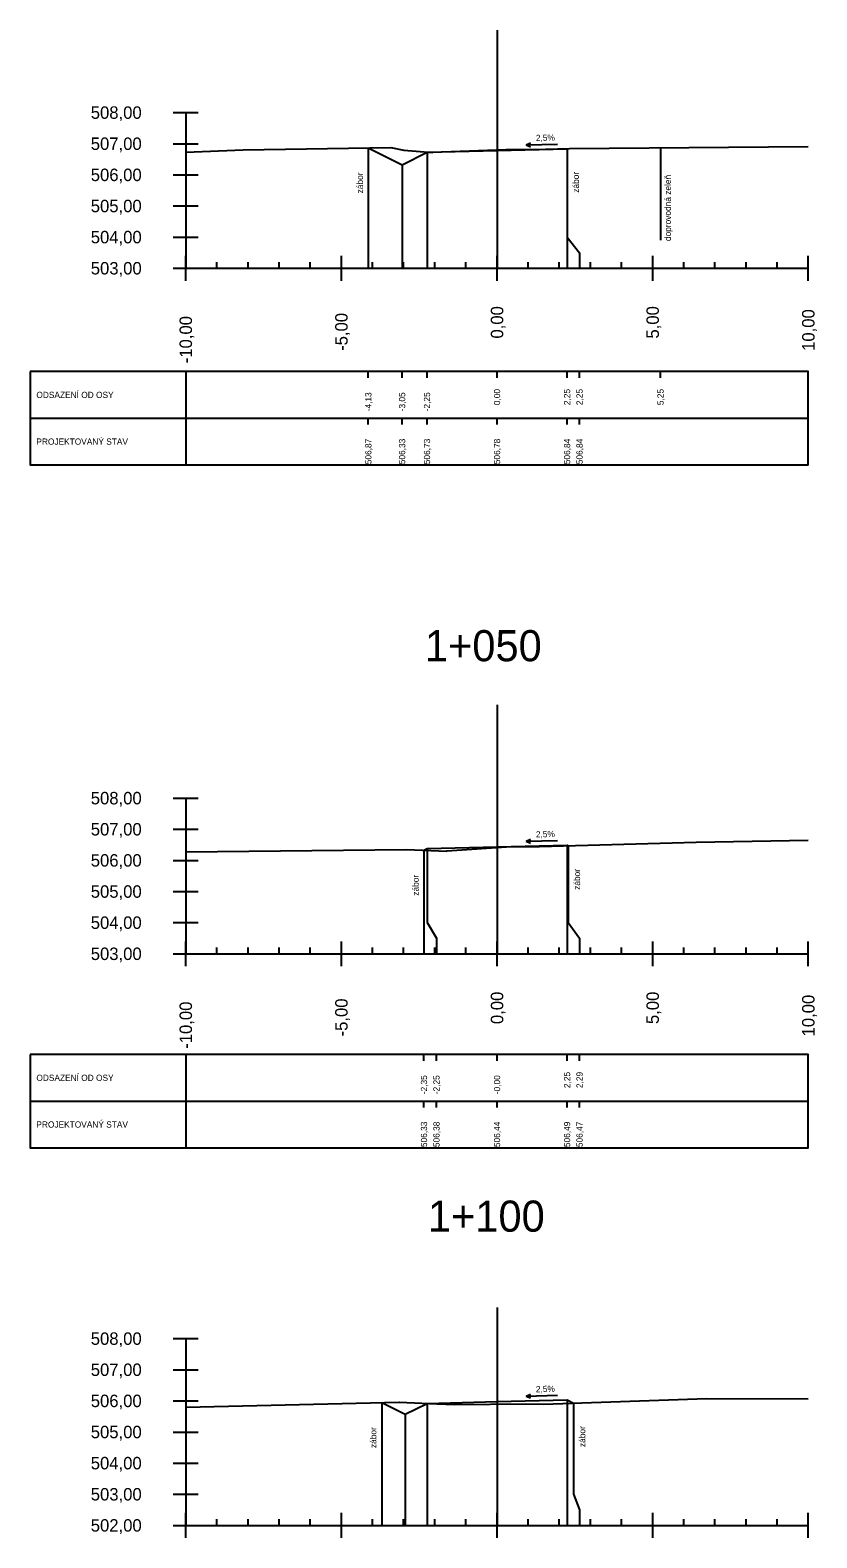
# Model space of a CAD drawing. Extents: x -631407 to -631215, y -1089700 to -1088598.
# Drawn here: x -631344.23 to -631318.96, y -1088856.74 to -1088808.31 of the extents above; entities that cross this region are included whole.
import ezdxf

# ---------------------------------------------------------------- set-up
doc = ezdxf.new("R2010")
doc.units = 0
for name, color, linetype in [('59', 7, 'Continuous'), ('NIVELETA_VYSKY', 7, 'Continuous'), ('REZ_BODY', 7, 'Continuous'), ('REZ_ODSTUPY', 7, 'Continuous'), ('REZ_POPIS', 7, 'Continuous'), ('REZ_RAMY', 7, 'Continuous'), ('REZ_STANICENI', 7, 'Continuous'), ('REZ_SVISLE', 7, 'Continuous'), ('REZ_TENKA', 7, 'Continuous'), ('REZ_TLUSTA', 7, 'Continuous'), ('TABULKA_POPIS', 7, 'Continuous'), ('TEREN', 7, 'Continuous'), ('zábor', 7, 'Continuous')]:
    doc.layers.add(name, color=color, linetype=linetype)

msp = doc.modelspace()

# ---------------------------------------------------------------- linework, layer by layer
at = {"layer": '59'}
for p, q in [((-631339.63, -1088810.959), (-631338.83, -1088810.959)), ((-631339.23, -1088810.959), (-631339.23, -1088815.959)), ((-631339.63, -1088811.959), (-631338.83, -1088811.959)), ((-631339.63, -1088812.959), (-631338.83, -1088812.959)), ((-631339.63, -1088813.959), (-631338.83, -1088813.959)), ((-631339.63, -1088814.959), (-631338.83, -1088814.959)), ((-631339.63, -1088815.959), (-631338.83, -1088815.959)), ((-631339.63, -1088832.981), (-631338.83, -1088832.981)), ((-631339.23, -1088832.981), (-631339.23, -1088837.981)), ((-631339.63, -1088833.981), (-631338.83, -1088833.981)), ((-631339.63, -1088834.981), (-631338.83, -1088834.981)), ((-631339.63, -1088835.981), (-631338.83, -1088835.981)), ((-631339.63, -1088836.981), (-631338.83, -1088836.981)), ((-631339.63, -1088837.981), (-631338.83, -1088837.981)), ((-631339.63, -1088850.343), (-631338.83, -1088850.343)), ((-631339.23, -1088850.343), (-631339.23, -1088856.343)), ((-631339.63, -1088851.343), (-631338.83, -1088851.343)), ((-631339.63, -1088852.343), (-631338.83, -1088852.343)), ((-631339.63, -1088853.343), (-631338.83, -1088853.343)), ((-631339.63, -1088854.343), (-631338.83, -1088854.343)), ((-631339.63, -1088855.343), (-631338.83, -1088855.343)), ((-631339.63, -1088856.343), (-631338.83, -1088856.343))]:
    msp.add_line(p, q, dxfattribs=at)
at = {"layer": 'REZ_RAMY'}
for p, q in [((-631339.23, -1088819.278), (-631339.23, -1088822.278)), ((-631333.365, -1088819.478), (-631333.365, -1088819.278)), ((-631332.28, -1088819.478), (-631332.28, -1088819.278)), ((-631331.48, -1088819.478), (-631331.48, -1088819.278)), ((-631329.23, -1088819.478), (-631329.23, -1088819.278)), ((-631326.98, -1088819.478), (-631326.98, -1088819.278)), ((-631326.58, -1088819.478), (-631326.58, -1088819.278)), ((-631323.979, -1088819.478), (-631323.979, -1088819.278)), ((-631344.23, -1088820.778), (-631319.23, -1088820.778)), ((-631333.365, -1088820.978), (-631333.365, -1088820.778)), ((-631332.28, -1088820.978), (-631332.28, -1088820.778)), ((-631331.48, -1088820.978), (-631331.48, -1088820.778)), ((-631329.23, -1088820.978), (-631329.23, -1088820.778)), ((-631326.98, -1088820.978), (-631326.98, -1088820.778)), ((-631326.58, -1088820.978), (-631326.58, -1088820.778)), ((-631344.23, -1088841.215), (-631344.23, -1088844.215)), ((-631339.23, -1088841.215), (-631339.23, -1088844.215)), ((-631331.577, -1088841.415), (-631331.577, -1088841.215)), ((-631331.177, -1088841.415), (-631331.177, -1088841.215)), ((-631329.23, -1088841.415), (-631329.23, -1088841.215)), ((-631326.98, -1088841.415), (-631326.98, -1088841.215)), ((-631326.58, -1088841.415), (-631326.58, -1088841.215)), ((-631344.23, -1088842.715), (-631319.23, -1088842.715)), ((-631331.577, -1088842.915), (-631331.577, -1088842.715)), ((-631331.177, -1088842.915), (-631331.177, -1088842.715)), ((-631329.23, -1088842.915), (-631329.23, -1088842.715)), ((-631326.98, -1088842.915), (-631326.98, -1088842.715)), ((-631326.58, -1088842.915), (-631326.58, -1088842.715))]:
    msp.add_line(p, q, dxfattribs=at)
for points in [[(-631344.23, -1088819.278), (-631344.23, -1088822.278), (-631319.23, -1088822.278), (-631319.23, -1088819.278)], [(-631344.23, -1088841.215), (-631344.23, -1088844.215), (-631319.23, -1088844.215), (-631319.23, -1088841.215)]]:
    msp.add_lwpolyline(points, close=True, dxfattribs=at)
at = {"layer": 'REZ_SVISLE'}
for points in [[(-631333.365, -1088812.089), (-631333.365, -1088814.959), (-631333.365, -1088815.459), (-631333.365, -1088815.959)], [(-631331.48, -1088812.232), (-631331.48, -1088814.959), (-631331.48, -1088815.459), (-631331.48, -1088815.959)], [(-631329.23, -1088812.175), (-631329.23, -1088814.959), (-631329.23, -1088815.459), (-631329.23, -1088815.959)], [(-631326.98, -1088812.119), (-631326.98, -1088814.959), (-631326.98, -1088815.459), (-631326.98, -1088815.959)], [(-631326.979, -1088812.119), (-631326.979, -1088814.959), (-631326.58, -1088815.459), (-631326.58, -1088815.959)], [(-631332.28, -1088812.632), (-631332.28, -1088814.959), (-631332.28, -1088815.459), (-631332.28, -1088815.959)], [(-631331.577, -1088834.651), (-631331.577, -1088836.981), (-631331.577, -1088837.481), (-631331.577, -1088837.981)], [(-631331.48, -1088834.602), (-631331.48, -1088836.981), (-631331.177, -1088837.481), (-631331.177, -1088837.981)], [(-631329.23, -1088834.546), (-631329.23, -1088836.981), (-631329.23, -1088837.481), (-631329.23, -1088837.981)], [(-631326.98, -1088834.49), (-631326.98, -1088836.981), (-631326.98, -1088837.481), (-631326.98, -1088837.981)], [(-631326.943, -1088834.511), (-631326.943, -1088836.981), (-631326.58, -1088837.481), (-631326.58, -1088837.981)], [(-631332.936, -1088852.395), (-631332.936, -1088855.343), (-631332.936, -1088855.843), (-631332.936, -1088856.343)], [(-631331.48, -1088852.424), (-631331.48, -1088855.343), (-631331.48, -1088855.843), (-631331.48, -1088856.343)], [(-631329.23, -1088852.367), (-631329.23, -1088855.343), (-631329.23, -1088855.843), (-631329.23, -1088856.343)], [(-631326.98, -1088852.311), (-631326.98, -1088855.343), (-631326.98, -1088855.843), (-631326.98, -1088856.343)], [(-631326.776, -1088852.413), (-631326.776, -1088855.343), (-631326.58, -1088855.843), (-631326.58, -1088856.343)], [(-631332.18, -1088852.774), (-631332.18, -1088855.343), (-631332.18, -1088855.843), (-631332.18, -1088856.343)]]:
    msp.add_lwpolyline(points, dxfattribs=at)
at = {"layer": 'REZ_TENKA'}
for p, q in [((-631338.23, -1088815.959), (-631338.23, -1088815.759)), ((-631337.23, -1088815.959), (-631337.23, -1088815.759)), ((-631336.23, -1088815.959), (-631336.23, -1088815.759)), ((-631335.23, -1088815.959), (-631335.23, -1088815.759)), ((-631333.23, -1088815.959), (-631333.23, -1088815.759)), ((-631332.23, -1088815.959), (-631332.23, -1088815.759)), ((-631331.23, -1088815.959), (-631331.23, -1088815.759)), ((-631330.23, -1088815.959), (-631330.23, -1088815.759)), ((-631328.23, -1088815.959), (-631328.23, -1088815.759)), ((-631327.23, -1088815.959), (-631327.23, -1088815.759)), ((-631326.23, -1088815.959), (-631326.23, -1088815.759)), ((-631325.23, -1088815.959), (-631325.23, -1088815.759)), ((-631323.23, -1088815.959), (-631323.23, -1088815.759)), ((-631322.23, -1088815.959), (-631322.23, -1088815.759)), ((-631321.23, -1088815.959), (-631321.23, -1088815.759)), ((-631320.23, -1088815.959), (-631320.23, -1088815.759)), ((-631338.23, -1088837.981), (-631338.23, -1088837.781)), ((-631337.23, -1088837.981), (-631337.23, -1088837.781)), ((-631336.23, -1088837.981), (-631336.23, -1088837.781)), ((-631335.23, -1088837.981), (-631335.23, -1088837.781)), ((-631333.23, -1088837.981), (-631333.23, -1088837.781)), ((-631332.23, -1088837.981), (-631332.23, -1088837.781)), ((-631331.23, -1088837.981), (-631331.23, -1088837.781)), ((-631330.23, -1088837.981), (-631330.23, -1088837.781)), ((-631328.23, -1088837.981), (-631328.23, -1088837.781)), ((-631327.23, -1088837.981), (-631327.23, -1088837.781)), ((-631326.23, -1088837.981), (-631326.23, -1088837.781)), ((-631325.23, -1088837.981), (-631325.23, -1088837.781)), ((-631323.23, -1088837.981), (-631323.23, -1088837.781)), ((-631322.23, -1088837.981), (-631322.23, -1088837.781)), ((-631321.23, -1088837.981), (-631321.23, -1088837.781)), ((-631320.23, -1088837.981), (-631320.23, -1088837.781)), ((-631338.23, -1088856.343), (-631338.23, -1088856.143)), ((-631337.23, -1088856.343), (-631337.23, -1088856.143)), ((-631336.23, -1088856.343), (-631336.23, -1088856.143)), ((-631335.23, -1088856.343), (-631335.23, -1088856.143)), ((-631333.23, -1088856.343), (-631333.23, -1088856.143)), ((-631332.23, -1088856.343), (-631332.23, -1088856.143)), ((-631331.23, -1088856.343), (-631331.23, -1088856.143)), ((-631330.23, -1088856.343), (-631330.23, -1088856.143)), ((-631328.23, -1088856.343), (-631328.23, -1088856.143)), ((-631327.23, -1088856.343), (-631327.23, -1088856.143)), ((-631326.23, -1088856.343), (-631326.23, -1088856.143)), ((-631325.23, -1088856.343), (-631325.23, -1088856.143)), ((-631323.23, -1088856.343), (-631323.23, -1088856.143)), ((-631322.23, -1088856.343), (-631322.23, -1088856.143)), ((-631321.23, -1088856.343), (-631321.23, -1088856.143)), ((-631320.23, -1088856.343), (-631320.23, -1088856.143))]:
    msp.add_line(p, q, dxfattribs=at)
at = {"layer": 'REZ_TLUSTA'}
for p, q in [((-631329.23, -1088808.311), (-631329.23, -1088815.959)), ((-631339.23, -1088816.359), (-631339.23, -1088815.559)), ((-631334.23, -1088816.359), (-631334.23, -1088815.559)), ((-631329.23, -1088816.359), (-631329.23, -1088815.559)), ((-631324.23, -1088816.359), (-631324.23, -1088815.559)), ((-631319.23, -1088816.359), (-631319.23, -1088815.559)), ((-631339.23, -1088815.959), (-631319.23, -1088815.959)), ((-631329.23, -1088829.981), (-631329.23, -1088837.981)), ((-631339.23, -1088838.381), (-631339.23, -1088837.581)), ((-631339.23, -1088837.981), (-631319.23, -1088837.981)), ((-631334.23, -1088838.381), (-631334.23, -1088837.581)), ((-631329.23, -1088838.381), (-631329.23, -1088837.581)), ((-631324.23, -1088838.381), (-631324.23, -1088837.581)), ((-631319.23, -1088838.381), (-631319.23, -1088837.581)), ((-631329.23, -1088849.343), (-631329.23, -1088856.343)), ((-631339.23, -1088856.743), (-631339.23, -1088855.943)), ((-631334.23, -1088856.743), (-631334.23, -1088855.943)), ((-631329.23, -1088856.743), (-631329.23, -1088855.943)), ((-631324.23, -1088856.743), (-631324.23, -1088855.943)), ((-631319.23, -1088856.743), (-631319.23, -1088855.943)), ((-631339.23, -1088856.343), (-631319.23, -1088856.343))]:
    msp.add_line(p, q, dxfattribs=at)
at = {"layer": 'TEREN'}
for points in [[(-631339.23, -1088812.227), (-631337.389, -1088812.151), (-631332.646, -1088812.078), (-631332.224, -1088812.165), (-631331.308, -1088812.237), (-631331.296, -1088812.232), (-631328.949, -1088812.144), (-631327.972, -1088812.146), (-631327.669, -1088812.138), (-631326.901, -1088812.117), (-631319.23, -1088812.043)], [(-631333.365, -1088812.089), (-631332.28, -1088812.632), (-631331.48, -1088812.232), (-631329.23, -1088812.175), (-631326.98, -1088812.119), (-631326.979, -1088812.119)], [(-631339.23, -1088834.71), (-631332.134, -1088834.628), (-631330.847, -1088834.68), (-631330.839, -1088834.676), (-631328.763, -1088834.535), (-631327.865, -1088834.537), (-631322.837, -1088834.399), (-631319.23, -1088834.328)], [(-631331.577, -1088834.651), (-631331.48, -1088834.602), (-631329.23, -1088834.546), (-631326.98, -1088834.49), (-631326.943, -1088834.511)], [(-631339.23, -1088852.54), (-631332.387, -1088852.383), (-631332.359, -1088852.382), (-631331.165, -1088852.442), (-631330.583, -1088852.464), (-631328.309, -1088852.441), (-631327.738, -1088852.445), (-631322.491, -1088852.268), (-631319.23, -1088852.273)], [(-631332.936, -1088852.395), (-631332.18, -1088852.774), (-631331.48, -1088852.424), (-631329.23, -1088852.367), (-631326.98, -1088852.311), (-631326.776, -1088852.413)]]:
    msp.add_lwpolyline(points, dxfattribs=at)
at = {"layer": 'zábor'}
for p, q in [((-631328.297, -1088811.996), (-631328.16, -1088811.931)), ((-631328.297, -1088811.996), (-631327.289, -1088811.971)), ((-631328.297, -1088811.996), (-631328.157, -1088812.054)), ((-631323.979, -1088812.089), (-631323.979, -1088815.062)), ((-631328.297, -1088834.366), (-631328.16, -1088834.302)), ((-631328.297, -1088834.366), (-631327.289, -1088834.341)), ((-631328.297, -1088834.366), (-631328.157, -1088834.424)), ((-631328.297, -1088852.188), (-631328.16, -1088852.123)), ((-631328.297, -1088852.188), (-631327.289, -1088852.163)), ((-631328.297, -1088852.188), (-631328.157, -1088852.245))]:
    msp.add_line(p, q, dxfattribs=at)

# ---------------------------------------------------------------- texts
at = {"layer": 'NIVELETA_VYSKY'}
for s, p in [('506,87', (-631333.265, -1088822.254)), ('506,33', (-631332.18, -1088822.254)), ('506,73', (-631331.38, -1088822.254)), ('506,78', (-631329.13, -1088822.254)), ('506,84', (-631326.88, -1088822.254)), ('506,84', (-631326.48, -1088822.254)), ('506,33', (-631331.477, -1088844.191)), ('506,38', (-631331.077, -1088844.191)), ('506,44', (-631329.13, -1088844.191)), ('506,49', (-631326.88, -1088844.191)), ('506,47', (-631326.48, -1088844.191))]:
    msp.add_text(s, height=0.2, rotation=90, dxfattribs=at).set_placement(p)
at = {"layer": 'REZ_BODY'}
for s, p in [('-4,13', (-631333.265, -1088820.555)), ('-3,05', (-631332.18, -1088820.555)), ('-2,25', (-631331.38, -1088820.555)), ('0,00', (-631329.13, -1088820.357)), ('2,25', (-631326.88, -1088820.357)), ('2,25', (-631326.48, -1088820.357)), ('5,25', (-631323.879, -1088820.357)), ('-2,35', (-631331.477, -1088842.492)), ('-2,25', (-631331.077, -1088842.492)), ('-0,00', (-631329.13, -1088842.492)), ('2,25', (-631326.88, -1088842.294)), ('2,29', (-631326.48, -1088842.294))]:
    msp.add_text(s, height=0.2, rotation=90, dxfattribs=at).set_placement(p)
at = {"layer": 'REZ_ODSTUPY'}
for s, p in [('0,00', (-631329.03, -1088818.218)), ('5,00', (-631324.03, -1088818.218)), ('-10,00', (-631339.03, -1088819.011)), ('-5,00', (-631334.03, -1088818.614)), ('10,00', (-631319.03, -1088818.614)), ('-5,00', (-631334.03, -1088840.636)), ('0,00', (-631329.03, -1088840.239)), ('5,00', (-631324.03, -1088840.239)), ('10,00', (-631319.03, -1088840.636)), ('-10,00', (-631339.03, -1088841.033))]:
    msp.add_text(s, height=0.4, rotation=90, dxfattribs=at).set_placement(p)
at = {"layer": 'REZ_POPIS'}
for s, p in [('508,00', (-631342.282, -1088811.159)), ('507,00', (-631342.282, -1088812.159)), ('506,00', (-631342.282, -1088813.159)), ('505,00', (-631342.282, -1088814.159)), ('504,00', (-631342.282, -1088815.159)), ('503,00', (-631342.282, -1088816.159)), ('508,00', (-631342.282, -1088833.181)), ('507,00', (-631342.282, -1088834.181)), ('506,00', (-631342.282, -1088835.181)), ('505,00', (-631342.282, -1088836.181)), ('504,00', (-631342.282, -1088837.181)), ('503,00', (-631342.282, -1088838.181)), ('508,00', (-631342.282, -1088850.543)), ('507,00', (-631342.282, -1088851.543)), ('506,00', (-631342.282, -1088852.543)), ('505,00', (-631342.282, -1088853.543)), ('504,00', (-631342.282, -1088854.543)), ('503,00', (-631342.282, -1088855.543)), ('502,00', (-631342.282, -1088856.543))]:
    msp.add_text(s, height=0.4, dxfattribs=at).set_placement(p)
at = {"layer": 'REZ_STANICENI'}
for s, p in [('1+050', (-631331.549, -1088828.584)), ('1+100', (-631331.453, -1088846.909))]:
    msp.add_text(s, height=1, dxfattribs=at).set_placement(p)
at = {"layer": 'TABULKA_POPIS'}
for s, p in [('ODSAZENÍ OD OSY', (-631344.03, -1088820.128)), ('PROJEKTOVANÝ STAV', (-631344.03, -1088821.628)), ('ODSAZENÍ OD OSY', (-631344.03, -1088842.065)), ('PROJEKTOVANÝ STAV', (-631344.03, -1088843.565))]:
    msp.add_text(s, height=0.2, dxfattribs=at).set_placement(p)
at = {"layer": 'zábor'}
for s, rotation, p in [('2,5%', 1.4321, (-631327.98, -1088811.875)), ('zábor', 90, (-631333.535, -1088813.553)), ('zábor', 90, (-631326.597, -1088813.534)), ('doprovodná zeleň', 90, (-631323.644, -1088815.086)), ('2,5%', 1.4321, (-631327.98, -1088834.245)), ('zábor', 90, (-631331.747, -1088836.114)), ('zábor', 90, (-631326.561, -1088835.926)), ('2,5%', 1.4321, (-631327.98, -1088852.067)), ('zábor', 90, (-631333.106, -1088853.859)), ('zábor', 90, (-631326.393, -1088853.827))]:
    msp.add_text(s, height=0.2, rotation=rotation, dxfattribs=at).set_placement(p)

doc.saveas('drawing.dxf')
